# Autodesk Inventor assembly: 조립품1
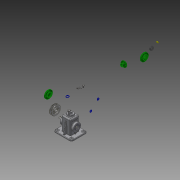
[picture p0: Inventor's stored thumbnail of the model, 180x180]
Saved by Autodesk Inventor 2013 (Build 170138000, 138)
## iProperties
Created: 2016-01
Part Number: 조립품1
Document SubType Name: Assembly
Designer: Administrator
Author: Administrator
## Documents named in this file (19)
- C:\Users\Administrator\Desktop\460127V1009\조립품1.iam
- C:\Users\Administrator\Desktop\460127V1009\부품1.ipt
- C:\Users\Administrator\Desktop\460127V1009\V-벨트풀리.ipt
- C:\Users\Administrator\Desktop\460127V1009\고정핀.ipt
- C:\Users\Administrator\Desktop\460127V1009\뒤커버.ipt
- C:\Users\Administrator\Desktop\460127V1009\링크.ipt
- C:\Users\Administrator\Desktop\460127V1009\멈춤링 6 x 5.ipt
- C:\Users\Administrator\Desktop\460127V1009\멈춤링 15 x 1.ipt
- C:\Users\Administrator\Desktop\460127V1009\베어링 15 x 35 x 11.ipt
- C:\Users\Administrator\Desktop\460127V1009\볼트 M3 x 8.ipt
- C:\Users\Administrator\Desktop\460127V1009\볼트 M4 x 10.ipt
- C:\Users\Administrator\Desktop\460127V1009\볼트 M6 x 12.ipt
- C:\Users\Administrator\Desktop\460127V1009\상부부시.ipt
- C:\Users\Administrator\Desktop\460127V1009\슬라이드바.ipt
- C:\Users\Administrator\Desktop\460127V1009\앞커버.ipt
- C:\Users\Administrator\Desktop\460127V1009\오일실 15 25 7.ipt
- C:\Users\Administrator\Desktop\460127V1009\와셔.ipt
- C:\Users\Administrator\Desktop\460127V1009\키 5 x 5 x 14.ipt
- C:\Users\Administrator\Desktop\460127V1009\편심축.ipt
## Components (5 placed, 5 different names)
1. V-벨트풀리:1
2. 고정핀:1
3. ISO 4762 M3 x 8:1
4. ISO 4762 M4 x 10:1
5. ISO 4018 M6 x 12:1
